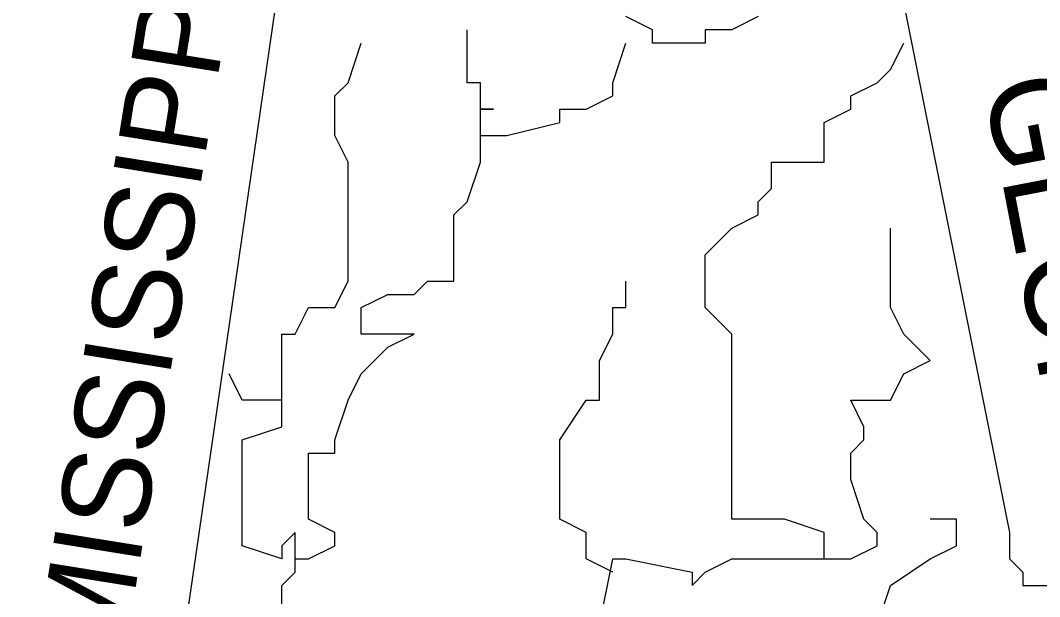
# Model space of a CAD drawing. Extents: x 515543 to 517243, y 660510 to 662861.
# Drawn here: x 516458.4 to 516478.65, y 660559.99 to 660571.44 of the extents above; entities that cross this region are included whole.
import ezdxf

# ---------------------------------------------------------------- set-up
doc = ezdxf.new("R2010")
doc.units = 0
doc.layers.add('great seal', color=7, linetype='Continuous')

msp = doc.modelspace()

# ---------------------------------------------------------------- linework, layer by layer
at = {"layer": 'great seal'}
msp.add_line((516470.166, 660560.477), (516470.166, 660560.477), dxfattribs=at)
msp.add_line((516470.166, 660560.477), (516470.166, 660560.477), dxfattribs=at)
msp.add_line((516470.166, 660560.477), (516470.166, 660560.477), dxfattribs=at)
msp.add_line((516470.166, 660560.477), (516470.166, 660560.477), dxfattribs=at)
msp.add_line((516470.166, 660560.477), (516470.166, 660560.477), dxfattribs=at)
msp.add_line((516470.166, 660560.477), (516470.166, 660560.477), dxfattribs=at)
for points in [[(516475.684, 660573.089), (516478.049, 660561.265), (516478.049, 660560.739), (516478.312, 660560.477), (516478.312, 660560.214), (516478.312, 660560.214), (516478.837, 660560.214)], [(516475.684, 660573.089), (516478.049, 660561.265), (516478.049, 660560.739), (516478.312, 660560.477), (516478.312, 660560.214), (516478.312, 660560.214), (516478.837, 660560.214)], [(516475.684, 660573.089), (516478.049, 660561.265), (516478.049, 660560.739), (516478.312, 660560.477), (516478.312, 660560.214), (516478.312, 660560.214), (516478.837, 660560.214)], [(516461.232, 660547.076), (516461.232, 660556.272), (516463.597, 660572.564)], [(516461.232, 660547.076), (516461.232, 660556.272), (516463.597, 660572.564)], [(516461.232, 660547.076), (516461.232, 660556.272), (516463.597, 660572.564)], [(516473.056, 660571.513), (516472.531, 660571.25), (516472.268, 660571.25), (516472.005, 660571.25), (516472.005, 660570.987), (516471.743, 660570.987), (516471.743, 660570.987), (516470.954, 660570.987), (516470.954, 660570.987), (516470.954, 660571.25), (516470.429, 660571.513)], [(516473.056, 660571.513), (516472.531, 660571.25), (516472.268, 660571.25), (516472.005, 660571.25), (516472.005, 660570.987), (516471.743, 660570.987), (516471.743, 660570.987), (516470.954, 660570.987), (516470.954, 660570.987), (516470.954, 660571.25), (516470.429, 660571.513)], [(516473.056, 660571.513), (516472.531, 660571.25), (516472.268, 660571.25), (516472.005, 660571.25), (516472.005, 660570.987), (516471.743, 660570.987), (516471.743, 660570.987), (516470.954, 660570.987), (516470.954, 660570.987), (516470.954, 660571.25), (516470.429, 660571.513)], [(516467.538, 660569.148), (516467.538, 660569.411), (516467.538, 660569.673), (516467.801, 660569.673), (516467.538, 660569.673), (516467.538, 660569.936), (516467.538, 660570.199), (516467.276, 660570.199), (516467.276, 660570.462), (516467.276, 660570.987), (516467.276, 660571.25)], [(516467.538, 660569.148), (516467.538, 660569.411), (516467.538, 660569.673), (516467.801, 660569.673), (516467.538, 660569.673), (516467.538, 660569.936), (516467.538, 660570.199), (516467.276, 660570.199), (516467.276, 660570.462), (516467.276, 660570.987), (516467.276, 660571.25)], [(516467.538, 660569.148), (516467.538, 660569.411), (516467.538, 660569.673), (516467.801, 660569.673), (516467.538, 660569.673), (516467.538, 660569.936), (516467.538, 660570.199), (516467.276, 660570.199), (516467.276, 660570.462), (516467.276, 660570.987), (516467.276, 660571.25)], [(516463.597, 660563.892), (516463.597, 660564.418), (516463.597, 660564.681), (516463.597, 660565.206), (516463.86, 660565.206), (516464.122, 660565.732), (516464.648, 660565.732), (516464.911, 660566.257), (516464.911, 660567.308), (516464.911, 660567.834), (516464.911, 660568.097), (516464.911, 660568.622), (516464.648, 660569.148), (516464.648, 660569.673), (516464.648, 660569.936), (516464.911, 660570.199), (516465.173, 660570.987)], [(516463.597, 660563.892), (516463.597, 660564.418), (516463.597, 660564.681), (516463.597, 660565.206), (516463.86, 660565.206), (516464.122, 660565.732), (516464.648, 660565.732), (516464.911, 660566.257), (516464.911, 660567.308), (516464.911, 660567.834), (516464.911, 660568.097), (516464.911, 660568.622), (516464.648, 660569.148), (516464.648, 660569.673), (516464.648, 660569.936), (516464.911, 660570.199), (516465.173, 660570.987)], [(516463.597, 660563.892), (516463.597, 660564.418), (516463.597, 660564.681), (516463.597, 660565.206), (516463.86, 660565.206), (516464.122, 660565.732), (516464.648, 660565.732), (516464.911, 660566.257), (516464.911, 660567.308), (516464.911, 660567.834), (516464.911, 660568.097), (516464.911, 660568.622), (516464.648, 660569.148), (516464.648, 660569.673), (516464.648, 660569.936), (516464.911, 660570.199), (516465.173, 660570.987)], [(516463.86, 660560.739), (516463.86, 660560.739), (516464.122, 660560.739), (516464.122, 660560.739), (516464.648, 660561.002), (516464.648, 660561.265), (516464.122, 660561.528), (516464.122, 660561.528), (516464.122, 660562.316), (516464.122, 660562.841), (516464.648, 660562.841), (516464.648, 660563.104), (516464.911, 660563.892), (516465.173, 660564.418), (516465.699, 660564.944), (516466.224, 660565.206), (516465.699, 660565.206), (516465.173, 660565.206), (516465.173, 660565.732), (516465.699, 660565.995), (516465.699, 660565.995), (516466.224, 660565.995), (516466.487, 660566.257), (516466.487, 660566.257), (516467.013, 660566.257), (516467.013, 660566.783), (516467.013, 660567.308), (516467.013, 660567.308), (516467.013, 660567.571), (516467.276, 660567.834), (516467.538, 660568.622), (516467.538, 660568.622), (516467.538, 660569.148), (516467.801, 660569.148), (516468.064, 660569.148), (516468.064, 660569.148), (516469.115, 660569.411), (516469.115, 660569.673), (516469.64, 660569.673), (516470.166, 660569.936), (516470.166, 660570.199), (516470.429, 660570.987)], [(516463.86, 660560.739), (516463.86, 660560.739), (516464.122, 660560.739), (516464.122, 660560.739), (516464.648, 660561.002), (516464.648, 660561.265), (516464.122, 660561.528), (516464.122, 660561.528), (516464.122, 660562.316), (516464.122, 660562.841), (516464.648, 660562.841), (516464.648, 660563.104), (516464.911, 660563.892), (516465.173, 660564.418), (516465.699, 660564.944), (516466.224, 660565.206), (516465.699, 660565.206), (516465.173, 660565.206), (516465.173, 660565.732), (516465.699, 660565.995), (516465.699, 660565.995), (516466.224, 660565.995), (516466.487, 660566.257), (516466.487, 660566.257), (516467.013, 660566.257), (516467.013, 660566.783), (516467.013, 660567.308), (516467.013, 660567.308), (516467.013, 660567.571), (516467.276, 660567.834), (516467.538, 660568.622), (516467.538, 660568.622), (516467.538, 660569.148), (516467.801, 660569.148), (516468.064, 660569.148), (516468.064, 660569.148), (516469.115, 660569.411), (516469.115, 660569.673), (516469.64, 660569.673), (516470.166, 660569.936), (516470.166, 660570.199), (516470.429, 660570.987)], [(516463.86, 660560.739), (516463.86, 660560.739), (516464.122, 660560.739), (516464.122, 660560.739), (516464.648, 660561.002), (516464.648, 660561.265), (516464.122, 660561.528), (516464.122, 660561.528), (516464.122, 660562.316), (516464.122, 660562.841), (516464.648, 660562.841), (516464.648, 660563.104), (516464.911, 660563.892), (516465.173, 660564.418), (516465.699, 660564.944), (516466.224, 660565.206), (516465.699, 660565.206), (516465.173, 660565.206), (516465.173, 660565.732), (516465.699, 660565.995), (516465.699, 660565.995), (516466.224, 660565.995), (516466.487, 660566.257), (516466.487, 660566.257), (516467.013, 660566.257), (516467.013, 660566.783), (516467.013, 660567.308), (516467.013, 660567.308), (516467.013, 660567.571), (516467.276, 660567.834), (516467.538, 660568.622), (516467.538, 660568.622), (516467.538, 660569.148), (516467.801, 660569.148), (516468.064, 660569.148), (516468.064, 660569.148), (516469.115, 660569.411), (516469.115, 660569.673), (516469.64, 660569.673), (516470.166, 660569.936), (516470.166, 660570.199), (516470.429, 660570.987)], [(516474.37, 660560.739), (516474.37, 660561.265), (516473.582, 660561.528), (516473.319, 660561.528), (516472.531, 660561.528), (516472.531, 660562.841), (516472.531, 660562.841), (516472.531, 660563.104), (516472.531, 660563.892), (516472.531, 660564.418), (516472.531, 660565.206), (516472.005, 660565.732), (516472.005, 660566.783), (516472.531, 660567.308), (516473.056, 660567.571), (516473.056, 660567.834), (516473.319, 660568.097), (516473.319, 660568.622), (516474.37, 660568.622), (516474.37, 660569.148), (516474.37, 660569.411), (516474.896, 660569.673), (516474.896, 660569.936), (516475.421, 660570.199), (516475.684, 660570.462), (516475.947, 660570.987)], [(516474.37, 660560.739), (516474.37, 660561.265), (516473.582, 660561.528), (516473.319, 660561.528), (516472.531, 660561.528), (516472.531, 660562.841), (516472.531, 660562.841), (516472.531, 660563.104), (516472.531, 660563.892), (516472.531, 660564.418), (516472.531, 660565.206), (516472.005, 660565.732), (516472.005, 660566.783), (516472.531, 660567.308), (516473.056, 660567.571), (516473.056, 660567.834), (516473.319, 660568.097), (516473.319, 660568.622), (516474.37, 660568.622), (516474.37, 660569.148), (516474.37, 660569.411), (516474.896, 660569.673), (516474.896, 660569.936), (516475.421, 660570.199), (516475.684, 660570.462), (516475.947, 660570.987)], [(516474.37, 660560.739), (516474.37, 660561.265), (516473.582, 660561.528), (516473.319, 660561.528), (516472.531, 660561.528), (516472.531, 660562.841), (516472.531, 660562.841), (516472.531, 660563.104), (516472.531, 660563.892), (516472.531, 660564.418), (516472.531, 660565.206), (516472.005, 660565.732), (516472.005, 660566.783), (516472.531, 660567.308), (516473.056, 660567.571), (516473.056, 660567.834), (516473.319, 660568.097), (516473.319, 660568.622), (516474.37, 660568.622), (516474.37, 660569.148), (516474.37, 660569.411), (516474.896, 660569.673), (516474.896, 660569.936), (516475.421, 660570.199), (516475.684, 660570.462), (516475.947, 660570.987)], [(516469.903, 660559.425), (516470.166, 660560.739), (516470.429, 660560.739), (516471.743, 660560.477), (516471.743, 660560.214), (516472.005, 660560.477), (516472.531, 660560.739), (516473.319, 660560.739), (516474.37, 660560.739), (516474.896, 660560.739), (516475.421, 660561.002), (516475.421, 660561.265), (516475.158, 660561.528), (516475.158, 660561.528), (516474.896, 660562.316), (516474.896, 660562.841), (516475.158, 660563.104), (516475.158, 660563.367), (516474.896, 660563.892), (516475.684, 660563.892), (516475.947, 660564.418), (516476.472, 660564.681), (516475.947, 660565.206), (516475.947, 660565.206), (516475.684, 660565.732), (516475.684, 660566.257), (516475.684, 660567.308)], [(516469.903, 660559.425), (516470.166, 660560.739), (516470.429, 660560.739), (516471.743, 660560.477), (516471.743, 660560.214), (516472.005, 660560.477), (516472.531, 660560.739), (516473.319, 660560.739), (516474.37, 660560.739), (516474.896, 660560.739), (516475.421, 660561.002), (516475.421, 660561.265), (516475.158, 660561.528), (516475.158, 660561.528), (516474.896, 660562.316), (516474.896, 660562.841), (516475.158, 660563.104), (516475.158, 660563.367), (516474.896, 660563.892), (516475.684, 660563.892), (516475.947, 660564.418), (516476.472, 660564.681), (516475.947, 660565.206), (516475.947, 660565.206), (516475.684, 660565.732), (516475.684, 660566.257), (516475.684, 660567.308)], [(516469.903, 660559.425), (516470.166, 660560.739), (516470.429, 660560.739), (516471.743, 660560.477), (516471.743, 660560.214), (516472.005, 660560.477), (516472.531, 660560.739), (516473.319, 660560.739), (516474.37, 660560.739), (516474.896, 660560.739), (516475.421, 660561.002), (516475.421, 660561.265), (516475.158, 660561.528), (516475.158, 660561.528), (516474.896, 660562.316), (516474.896, 660562.841), (516475.158, 660563.104), (516475.158, 660563.367), (516474.896, 660563.892), (516475.684, 660563.892), (516475.947, 660564.418), (516476.472, 660564.681), (516475.947, 660565.206), (516475.947, 660565.206), (516475.684, 660565.732), (516475.684, 660566.257), (516475.684, 660567.308)], [(516470.166, 660560.477), (516469.64, 660560.739), (516469.64, 660561.002), (516469.64, 660561.265), (516469.115, 660561.528), (516469.115, 660562.316), (516469.115, 660562.841), (516469.115, 660563.104), (516469.115, 660563.104), (516469.64, 660563.892), (516469.903, 660563.892), (516469.903, 660564.681), (516470.166, 660565.206), (516470.166, 660565.206), (516470.166, 660565.732), (516470.429, 660565.732), (516470.429, 660566.257)], [(516470.166, 660560.477), (516469.64, 660560.739), (516469.64, 660561.002), (516469.64, 660561.265), (516469.115, 660561.528), (516469.115, 660562.316), (516469.115, 660562.841), (516469.115, 660563.104), (516469.115, 660563.104), (516469.64, 660563.892), (516469.903, 660563.892), (516469.903, 660564.681), (516470.166, 660565.206), (516470.166, 660565.206), (516470.166, 660565.732), (516470.429, 660565.732), (516470.429, 660566.257)], [(516470.166, 660560.477), (516469.64, 660560.739), (516469.64, 660561.002), (516469.64, 660561.265), (516469.115, 660561.528), (516469.115, 660562.316), (516469.115, 660562.841), (516469.115, 660563.104), (516469.115, 660563.104), (516469.64, 660563.892), (516469.903, 660563.892), (516469.903, 660564.681), (516470.166, 660565.206), (516470.166, 660565.206), (516470.166, 660565.732), (516470.429, 660565.732), (516470.429, 660566.257)], [(516463.597, 660559.163), (516463.597, 660560.214), (516463.597, 660560.214), (516463.86, 660560.477), (516463.86, 660560.739), (516463.86, 660561.265), (516463.597, 660561.002), (516463.597, 660560.739), (516462.809, 660561.002), (516462.809, 660561.265), (516462.809, 660561.528), (516462.809, 660561.528), (516462.809, 660562.841), (516462.809, 660562.841), (516462.809, 660563.104), (516463.597, 660563.367), (516463.597, 660563.892), (516462.809, 660563.892), (516462.546, 660564.418), (516462.546, 660564.418)], [(516463.597, 660559.163), (516463.597, 660560.214), (516463.597, 660560.214), (516463.86, 660560.477), (516463.86, 660560.739), (516463.86, 660561.265), (516463.597, 660561.002), (516463.597, 660560.739), (516462.809, 660561.002), (516462.809, 660561.265), (516462.809, 660561.528), (516462.809, 660561.528), (516462.809, 660562.841), (516462.809, 660562.841), (516462.809, 660563.104), (516463.597, 660563.367), (516463.597, 660563.892), (516462.809, 660563.892), (516462.546, 660564.418), (516462.546, 660564.418)], [(516463.597, 660559.163), (516463.597, 660560.214), (516463.597, 660560.214), (516463.86, 660560.477), (516463.86, 660560.739), (516463.86, 660561.265), (516463.597, 660561.002), (516463.597, 660560.739), (516462.809, 660561.002), (516462.809, 660561.265), (516462.809, 660561.528), (516462.809, 660561.528), (516462.809, 660562.841), (516462.809, 660562.841), (516462.809, 660563.104), (516463.597, 660563.367), (516463.597, 660563.892), (516462.809, 660563.892), (516462.546, 660564.418), (516462.546, 660564.418)], [(516471.743, 660553.645), (516471.743, 660553.645), (516471.743, 660554.433), (516472.005, 660554.696), (516472.005, 660554.958), (516472.005, 660555.484), (516472.268, 660555.484), (516472.531, 660556.01), (516473.319, 660556.272), (516473.582, 660556.798), (516474.37, 660556.798), (516474.37, 660557.323), (516474.896, 660558.374), (516474.896, 660558.9), (516474.896, 660558.9), (516474.896, 660559.163), (516475.158, 660559.163), (516475.421, 660559.425), (516475.684, 660560.214), (516476.472, 660560.739), (516476.998, 660561.002), (516476.998, 660561.265), (516476.998, 660561.528), (516476.472, 660561.528)], [(516471.743, 660553.645), (516471.743, 660553.645), (516471.743, 660554.433), (516472.005, 660554.696), (516472.005, 660554.958), (516472.005, 660555.484), (516472.268, 660555.484), (516472.531, 660556.01), (516473.319, 660556.272), (516473.582, 660556.798), (516474.37, 660556.798), (516474.37, 660557.323), (516474.896, 660558.374), (516474.896, 660558.9), (516474.896, 660558.9), (516474.896, 660559.163), (516475.158, 660559.163), (516475.421, 660559.425), (516475.684, 660560.214), (516476.472, 660560.739), (516476.998, 660561.002), (516476.998, 660561.265), (516476.998, 660561.528), (516476.472, 660561.528)], [(516471.743, 660553.645), (516471.743, 660553.645), (516471.743, 660554.433), (516472.005, 660554.696), (516472.005, 660554.958), (516472.005, 660555.484), (516472.268, 660555.484), (516472.531, 660556.01), (516473.319, 660556.272), (516473.582, 660556.798), (516474.37, 660556.798), (516474.37, 660557.323), (516474.896, 660558.374), (516474.896, 660558.9), (516474.896, 660558.9), (516474.896, 660559.163), (516475.158, 660559.163), (516475.421, 660559.425), (516475.684, 660560.214), (516476.472, 660560.739), (516476.998, 660561.002), (516476.998, 660561.265), (516476.998, 660561.528), (516476.472, 660561.528)]]:
    msp.add_lwpolyline(points, dxfattribs=at)
for radius in [22.994, 22.994, 22.994, 22.389, 22.389, 22.389, 17.779, 17.779, 17.779, 17.222, 17.222, 17.222]:
    msp.add_circle((516470.184, 660560.292), radius, dxfattribs=at)

# ---------------------------------------------------------------- texts
for s, height, rotation, p in [('MISSISSIPPI', 1.75474, 80.8531, (516460.444, 660558.637)), ('MISSISSIPPI', 1.75474, 80.8531, (516460.444, 660558.637)), ('MISSISSIPPI', 1.75474, 80.8531, (516460.444, 660558.637)), ('GEORGIA', 1.8446, 280.9296, (516477.523, 660570.199)), ('GEORGIA', 1.8446, 280.9296, (516477.523, 660570.199)), ('GEORGIA', 1.8446, 280.9296, (516477.523, 660570.199))]:
    msp.add_text(s, height=height, rotation=rotation, dxfattribs=at).set_placement(p)

doc.saveas('drawing.dxf')
